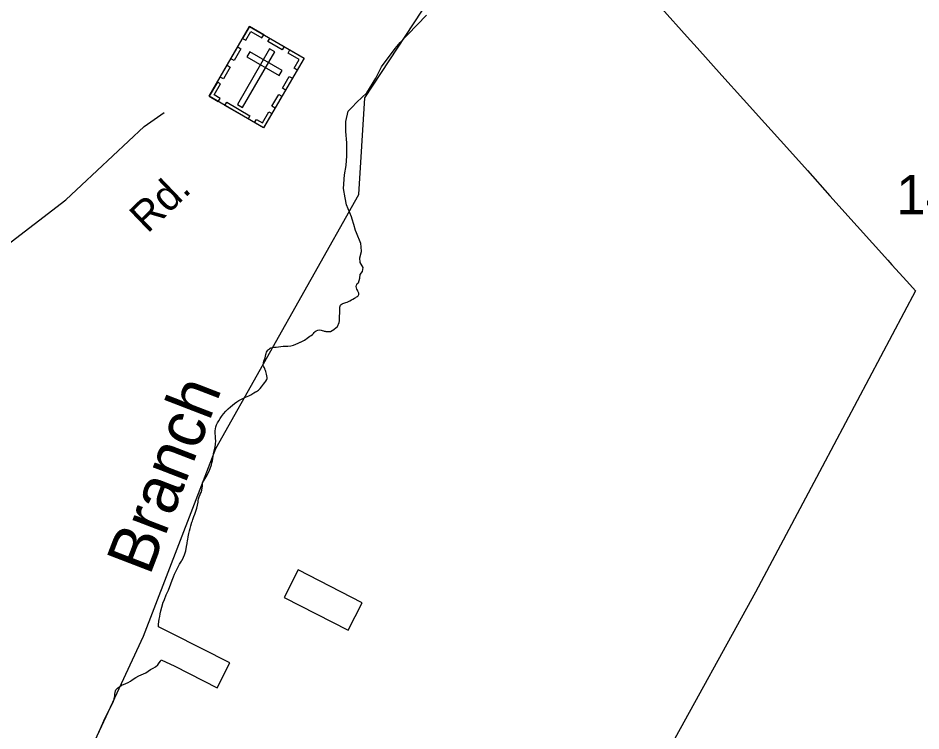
# Model space of a CAD drawing. Extents: x 2532689 to 2764727, y 536648 to 732970.
# Drawn here: x 2569863 to 2572716, y 677559 to 679813 of the extents above; entities that cross this region are included whole.
import ezdxf

# ---------------------------------------------------------------- set-up
doc = ezdxf.new("R2010")
doc.units = 0
for name, color, linetype in [('Exist Boundary Political City Limit New', 7, 'Continuous'), ('Exist Boundary Political City Limit New Hole', 7, 'Continuous'), ('Exist Cultural Cemetery CELL', 7, 'Continuous'), ('Exist Hydrographic Creek Single Shore', 7, 'Continuous'), ('Exist Hydrographic Creek Single Shore Label', 7, 'Continuous'), ('Exist Road Secondary Type 10 Attributed', 7, 'Continuous'), ('Exist Road Secondary Type 51 Label', 7, 'Continuous'), ('Exist Road Secondary Type 51 Number Label', 7, 'Continuous'), ('Map Preparation Boundary City Limit Buffer Line', 7, 'Continuous')]:
    doc.layers.add(name, color=color, linetype=linetype)

msp = doc.modelspace()

# ---------------------------------------------------------------- linework, layer by layer
at = {"layer": 'Exist Boundary Political City Limit New'}
for points in [[(2571895.8, 679844.9), (2571977.2, 679753.9)], [(2570860.8, 678828.7), (2570861.8, 678829.3), (2570872, 678838.1), (2570877.5, 678850), (2570878, 678855.6), (2570878, 678861), (2570878, 678864.5), (2570878, 678867.2), (2570878.5, 678872.9), (2570879, 678877.8), (2570879.5, 678882.4), (2570879.8, 678887.6), (2570879.8, 678893.1), (2570880, 678898.8), (2570880.2, 678902.1), (2570881.2, 678905.1), (2570883.5, 678907.6), (2570886.5, 678909.4), (2570889.2, 678910.4), (2570892, 678911.2), (2570898.5, 678913.4), (2570902.5, 678915.1), (2570905, 678916.2), (2570911.2, 678919.2), (2570916, 678921.7), (2570920.8, 678924.4), (2570926.2, 678927.6), (2570929.8, 678929.6), (2570932.5, 678931.2), (2570935.2, 678933.2), (2570937, 678935.1), (2570938.5, 678937.1), (2570939.5, 678939.2), (2570939.8, 678941), (2570939.5, 678942.9), (2570938.8, 678945.2), (2570936.8, 678949.8), (2570935, 678953.2), (2570933.5, 678956.4), (2570932.2, 678960.2), (2570931.5, 678964.3), (2570932, 678968.4), (2570933, 678971.1), (2570934.8, 678973.4), (2570937.5, 678975.6), (2570938.5, 678976.2), (2570943, 678991.2), (2570944.2, 679001.9), (2570950.8, 679011.8), (2570953.5, 679024.9), (2570944.2, 679040.6), (2570942.8, 679054.8), (2570947.5, 679075.3), (2570946.8, 679089.6), (2570946.2, 679100.6), (2570932.2, 679134.4), (2570929.5, 679141.2), (2570924, 679160.1), (2570919, 679177.2), (2570916, 679184.8), (2570901, 679222.8), (2570896.8, 679244.4), (2570890.8, 679274.4), (2570894, 679317.2), (2570899, 679347.2), (2570902, 679378), (2570902, 679418.4), (2570898.2, 679454.4), (2570898.2, 679485.6), (2570906.2, 679518.8), (2570917.2, 679530.4), (2570933, 679547.2), (2570965, 679576.4), (2570992.8, 679622.8), (2571006.8, 679650.2), (2571011.5, 679659.2), (2571054, 679717.2), (2571070.5, 679735.4), (2571094.2, 679761.2), (2571153.5, 679822.8)], [(2571977.2, 679753.9), (2572008.8, 679718.9), (2572087, 679631.7), (2572155, 679556), (2572222, 679481.3), (2572291.8, 679403.5), (2572356.8, 679331.1), (2572428.2, 679251.3), (2572514.2, 679155.6), (2572611.2, 679047.3), (2572624.2, 679033), (2572670.8, 678981.1), (2572698.2, 678950.5), (2572403.2, 678393.7), (2572193.2, 677997.9), (2571626.5, 676969)], [(2570511.5, 678561.6), (2570519.8, 678570.5), (2570527, 678577.4), (2570534, 678583.6), (2570540.2, 678588.8), (2570547, 678594.1), (2570554, 678599.2), (2570560.2, 678603.4), (2570566.8, 678607.2), (2570574.8, 678611.2), (2570581.2, 678614.1), (2570587, 678616.4), (2570592.2, 678618.8), (2570598.5, 678622.2), (2570604.8, 678626), (2570607.8, 678627.7), (2570613, 678630.8), (2570616.5, 678632.8), (2570622.2, 678636.5), (2570624.5, 678638.7), (2570628, 678642), (2570632.2, 678647.1), (2570635.2, 678651.7), (2570638.2, 678656), (2570642, 678660.6), (2570645.8, 678665.4), (2570648.8, 678670.4), (2570649.8, 678673.6), (2570649.8, 678677.1), (2570649.2, 678681.6), (2570648, 678687.1), (2570646.8, 678691.3), (2570645.5, 678695.2), (2570644.2, 678699), (2570643, 678703.1), (2570642.5, 678704.3), (2570641.2, 678707.2), (2570639.5, 678710.1), (2570638, 678712.9), (2570637.2, 678716.4), (2570637.8, 678723.2), (2570639.5, 678728.8), (2570641.5, 678734), (2570643.2, 678738.7), (2570644.8, 678743.7), (2570646.2, 678749.2), (2570647.2, 678753), (2570648, 678756.5), (2570650, 678760), (2570652.2, 678762.9), (2570654.5, 678765.2), (2570656.8, 678767.2), (2570658.2, 678768.4), (2570659.8, 678769.4), (2570660.5, 678769.7), (2570662, 678770.4), (2570667.8, 678772), (2570672.5, 678772.6), (2570675.8, 678772.7), (2570678, 678772.8), (2570686, 678773.6), (2570693.2, 678774.6), (2570700, 678775.2), (2570707.2, 678775.2), (2570715.2, 678775.4), (2570724.2, 678776.8), (2570732.8, 678779.2), (2570740, 678781.8), (2570747.5, 678785.2), (2570753.8, 678788), (2570755, 678788.5), (2570761.8, 678791.6), (2570768, 678794.8), (2570771.8, 678797.3), (2570776, 678800.3), (2570776.5, 678800.7), (2570780.8, 678804), (2570785.2, 678807.2), (2570789, 678809.8), (2570792.8, 678812.8), (2570795.8, 678815.8), (2570798.8, 678818.8), (2570801.5, 678821.6), (2570805.2, 678824.7), (2570809.8, 678826.8), (2570815.5, 678827.2), (2570820.2, 678826.5), (2570824, 678825.3), (2570828, 678824), (2570830.5, 678823.3), (2570833, 678822.8), (2570835.2, 678822.4), (2570837.2, 678822.2), (2570839.5, 678822.1), (2570842, 678822), (2570843.2, 678822), (2570845, 678822), (2570847.2, 678822), (2570849.5, 678822), (2570860.8, 678828.7)], [(2570309, 677912.3), (2570310.5, 677920.8), (2570312.2, 677929.7), (2570314.2, 677939.1), (2570317.2, 677950.9), (2570320.2, 677961.9), (2570320.5, 677962.9), (2570325, 677974.8), (2570331.2, 677989.4), (2570338.2, 678004.6), (2570345.8, 678024), (2570349.5, 678035.5), (2570353.5, 678046.8), (2570357, 678055.2), (2570361, 678063.6), (2570366.2, 678073.6), (2570373.2, 678085.9), (2570379.2, 678095.8), (2570380.2, 678097.6), (2570384.2, 678105.1), (2570385.8, 678108.6), (2570388.8, 678116.1), (2570392.5, 678128.3), (2570395.5, 678141.9), (2570397, 678152.2), (2570398.2, 678161.8), (2570398.8, 678164.7), (2570400.2, 678172.8), (2570402.5, 678182.9), (2570404.8, 678191.6), (2570406.8, 678199.6), (2570409, 678208), (2570412, 678219), (2570413.5, 678223.7), (2570414.8, 678227.6), (2570418, 678236.9), (2570420.8, 678244.1), (2570421, 678244.8), (2570424, 678253.6), (2570427.2, 678263.8), (2570429.8, 678273.2), (2570431.5, 678282), (2570431.8, 678284), (2570432.2, 678287.1), (2570433, 678292.6), (2570434.8, 678299.2), (2570438, 678307.1), (2570438.5, 678308.1), (2570441, 678313.4), (2570443.5, 678320), (2570445, 678327.8), (2570445.2, 678332.9), (2570445.5, 678335.7), (2570445.5, 678343.6), (2570450.5, 678351.9), (2570456.8, 678362.1), (2570466.8, 678380.9), (2570474, 678400.4), (2570475.5, 678406.4), (2570476.8, 678412.6), (2570478, 678420.4), (2570479.2, 678428.4), (2570480.5, 678434.8), (2570481.5, 678440.8), (2570484, 678451.9), (2570486.2, 678463.9), (2570486.5, 678466.2), (2570487.2, 678476), (2570487, 678483.3), (2570486.8, 678485.4), (2570486.2, 678490.6), (2570486, 678499.6), (2570486, 678507.8), (2570486.2, 678514.6), (2570487.5, 678520.8), (2570489.8, 678526.8), (2570493, 678533), (2570496.8, 678539.2), (2570501, 678546.6), (2570505.2, 678553.8), (2570511.5, 678561.6)], [(2570118, 677555.1), (2570123, 677566.7), (2570126.2, 677574.4), (2570133.5, 677591), (2570141, 677606.7), (2570143.2, 677611.1), (2570145.2, 677615.3), (2570149.8, 677624.2), (2570154.8, 677633.5), (2570158.2, 677639.8), (2570161.5, 677646), (2570164.2, 677653.5), (2570166, 677659.8), (2570166.8, 677663), (2570167.5, 677665.3), (2570168.2, 677670.7), (2570168.5, 677673.3), (2570168.8, 677675.7), (2570169.2, 677680.9), (2570170.8, 677685.9), (2570172, 677688.9), (2570173.8, 677691.6), (2570176.8, 677694.3), (2570177.2, 677694.7), (2570184, 677699.7), (2570190.2, 677703.4), (2570192.2, 677704.4), (2570196.2, 677706.3), (2570203.2, 677709.1), (2570210.8, 677712.2), (2570218.2, 677716.3), (2570223.5, 677720.2), (2570228.5, 677724.1), (2570230, 677725.2), (2570234.8, 677728.3), (2570244, 677732.9), (2570252, 677736.1), (2570259.5, 677739.1), (2570266.5, 677742.9), (2570273.8, 677747.6), (2570281.5, 677752.8), (2570289.5, 677757.4), (2570297, 677761.8), (2570304, 677768.3), (2570309, 677774), (2570312.8, 677779.3), (2570314.8, 677783.9), (2570357.8, 677763.4), (2570492.2, 677695.3), (2570532, 677774.2), (2570350.8, 677865.9), (2570306.2, 677888.6), (2570306.8, 677896), (2570307.8, 677904.8), (2570309, 677912.3)]]:
    msp.add_lwpolyline(points, dxfattribs=at)
at = {"layer": 'Exist Boundary Political City Limit New Hole'}
msp.add_lwpolyline([(2570703.5, 677981.3), (2570906.2, 677877.3), (2570950.2, 677964.2), (2570747.5, 678068.6), (2570703.5, 677981.3)], dxfattribs=at)
at = {"layer": 'Exist Cultural Cemetery CELL'}
for points in [[(2570594.2, 679786.1), (2570766.4, 679686.3), (2570638.8, 679466), (2570466.5, 679565.8)], [(2570572.4, 679748.7), (2570582.3, 679743), (2570598.4, 679770.8), (2570633.5, 679750.5), (2570639.1, 679760.1), (2570594.2, 679786.1)], [(2570658.2, 679749), (2570703.1, 679723), (2570697.4, 679713.1), (2570652.5, 679739.1)], [(2570535.2, 679684.5), (2570557, 679722), (2570566.8, 679716.3), (2570545.1, 679678.8)], [(2570673.8, 679706.1), (2570657.6, 679715.5), (2570556, 679540), (2570572.1, 679530.7)], [(2570595.3, 679706.8), (2570586, 679690.6), (2570687.9, 679631.6), (2570697.2, 679647.8)], [(2570744.7, 679648.8), (2570734.9, 679654.5), (2570751.1, 679682.3), (2570716, 679702.6), (2570721.5, 679712.3), (2570766.4, 679686.2)], [(2570501.5, 679626.3), (2570523.2, 679663.8), (2570533.1, 679658.1), (2570511.4, 679620.6)], [(2570698.2, 679591.3), (2570719.9, 679628.7), (2570729.8, 679623), (2570708.1, 679585.5)], [(2570495.1, 679549.3), (2570500.9, 679559.2), (2570481.9, 679570.2), (2570502.1, 679605.2), (2570492.5, 679610.8), (2570466.5, 679565.9)], [(2570665.1, 679534.2), (2570686.9, 679571.7), (2570696.7, 679566), (2570675, 679528.5)], [(2570522, 679546.9), (2570595.4, 679504.4), (2570589.7, 679494.5), (2570516.3, 679537.1)], [(2570610.1, 679482.6), (2570615.8, 679492.6), (2570634.9, 679481.5), (2570655.1, 679516.5), (2570664.8, 679510.9), (2570638.8, 679466)]]:
    msp.add_lwpolyline(points, close=True, dxfattribs=at)
at = {"layer": 'Exist Hydrographic Creek Single Shore'}
msp.add_lwpolyline([(2569856.8, 677104.4), (2570050.6, 677410.2), (2570258.8, 677858.6), (2570487.6, 678452.2), (2570939.7, 679255.2), (2570958.6, 679561.3), (2571241.8, 679993.1), (2571271.7, 680151.9), (2571468.8, 680297.7), (2571540.7, 680441.8), (2571618.7, 680717.5), (2571692.7, 680802.5), (2571973.6, 680925.5), (2572037.6, 681026.6), (2572130.7, 681417.8), (2572115.7, 681719.2), (2572080.6, 681842.6), (2572061.6, 682360.5), (2571991.7, 682557.9), (2571751.7, 682869.9)], dxfattribs=at)
at = {"layer": 'Exist Road Secondary Type 10 Attributed'}
msp.add_lwpolyline([(2569071.9, 678518.3), (2569725.7, 679018.3), (2570013.9, 679238.7), (2570261.6, 679469.9), (2570324.1, 679514.6)], dxfattribs=at)
at = {"layer": 'Map Preparation Boundary City Limit Buffer Line'}
for points in [[(2571895.8, 679844.9), (2571977.2, 679753.9)], [(2570860.8, 678828.7), (2570861.8, 678829.3), (2570872, 678838.1), (2570877.5, 678850), (2570878, 678855.6), (2570878, 678861), (2570878, 678864.5), (2570878, 678867.2), (2570878.5, 678872.9), (2570879, 678877.8), (2570879.5, 678882.4), (2570879.8, 678887.6), (2570879.8, 678893.1), (2570880, 678898.8), (2570880.2, 678902.1), (2570881.2, 678905.1), (2570883.5, 678907.6), (2570886.5, 678909.4), (2570889.2, 678910.4), (2570892, 678911.2), (2570898.5, 678913.4), (2570902.5, 678915.1), (2570905, 678916.2), (2570911.2, 678919.2), (2570916, 678921.7), (2570920.8, 678924.4), (2570926.2, 678927.6), (2570929.8, 678929.6), (2570932.5, 678931.2), (2570935.2, 678933.2), (2570937, 678935.1), (2570938.5, 678937.1), (2570939.5, 678939.2), (2570939.8, 678941), (2570939.5, 678942.9), (2570938.8, 678945.2), (2570936.8, 678949.8), (2570935, 678953.2), (2570933.5, 678956.4), (2570932.2, 678960.2), (2570931.5, 678964.3), (2570932, 678968.4), (2570933, 678971.1), (2570934.8, 678973.4), (2570937.5, 678975.6), (2570938.5, 678976.2), (2570943, 678991.2), (2570944.2, 679001.9), (2570950.8, 679011.8), (2570953.5, 679024.9), (2570944.2, 679040.6), (2570942.8, 679054.8), (2570947.5, 679075.3), (2570946.8, 679089.6), (2570946.2, 679100.6), (2570932.2, 679134.4), (2570929.5, 679141.2), (2570924, 679160.1), (2570919, 679177.2), (2570916, 679184.8), (2570901, 679222.8), (2570896.8, 679244.4), (2570890.8, 679274.4), (2570894, 679317.2), (2570899, 679347.2), (2570902, 679378), (2570902, 679418.4), (2570898.2, 679454.4), (2570898.2, 679485.6), (2570906.2, 679518.8), (2570917.2, 679530.4), (2570933, 679547.2), (2570965, 679576.4), (2570992.8, 679622.8), (2571006.8, 679650.2), (2571011.5, 679659.2), (2571054, 679717.2), (2571070.5, 679735.4), (2571094.2, 679761.2), (2571153.5, 679822.8)], [(2571977.2, 679753.9), (2572008.8, 679718.9), (2572087, 679631.7), (2572155, 679556), (2572222, 679481.3), (2572291.8, 679403.5), (2572356.8, 679331.1), (2572428.2, 679251.3), (2572514.2, 679155.6), (2572611.2, 679047.3), (2572624.2, 679033), (2572670.8, 678981.1), (2572698.2, 678950.5), (2572403.2, 678393.7), (2572193.2, 677997.9), (2571626.5, 676969)], [(2570511.5, 678561.6), (2570519.8, 678570.5), (2570527, 678577.4), (2570534, 678583.6), (2570540.2, 678588.8), (2570547, 678594.1), (2570554, 678599.2), (2570560.2, 678603.4), (2570566.8, 678607.2), (2570574.8, 678611.2), (2570581.2, 678614.1), (2570587, 678616.4), (2570592.2, 678618.8), (2570598.5, 678622.2), (2570604.8, 678626), (2570607.8, 678627.7), (2570613, 678630.8), (2570616.5, 678632.8), (2570622.2, 678636.5), (2570624.5, 678638.7), (2570628, 678642), (2570632.2, 678647.1), (2570635.2, 678651.7), (2570638.2, 678656), (2570642, 678660.6), (2570645.8, 678665.4), (2570648.8, 678670.4), (2570649.8, 678673.6), (2570649.8, 678677.1), (2570649.2, 678681.6), (2570648, 678687.1), (2570646.8, 678691.3), (2570645.5, 678695.2), (2570644.2, 678699), (2570643, 678703.1), (2570642.5, 678704.3), (2570641.2, 678707.2), (2570639.5, 678710.1), (2570638, 678712.9), (2570637.2, 678716.4), (2570637.8, 678723.2), (2570639.5, 678728.8), (2570641.5, 678734), (2570643.2, 678738.7), (2570644.8, 678743.7), (2570646.2, 678749.2), (2570647.2, 678753), (2570648, 678756.5), (2570650, 678760), (2570652.2, 678762.9), (2570654.5, 678765.2), (2570656.8, 678767.2), (2570658.2, 678768.4), (2570659.8, 678769.4), (2570660.5, 678769.7), (2570662, 678770.4), (2570667.8, 678772), (2570672.5, 678772.6), (2570675.8, 678772.7), (2570678, 678772.8), (2570686, 678773.6), (2570693.2, 678774.6), (2570700, 678775.2), (2570707.2, 678775.2), (2570715.2, 678775.4), (2570724.2, 678776.8), (2570732.8, 678779.2), (2570740, 678781.8), (2570747.5, 678785.2), (2570753.8, 678788), (2570755, 678788.5), (2570761.8, 678791.6), (2570768, 678794.8), (2570771.8, 678797.3), (2570776, 678800.3), (2570776.5, 678800.7), (2570780.8, 678804), (2570785.2, 678807.2), (2570789, 678809.8), (2570792.8, 678812.8), (2570795.8, 678815.8), (2570798.8, 678818.8), (2570801.5, 678821.6), (2570805.2, 678824.7), (2570809.8, 678826.8), (2570815.5, 678827.2), (2570820.2, 678826.5), (2570824, 678825.3), (2570828, 678824), (2570830.5, 678823.3), (2570833, 678822.8), (2570835.2, 678822.4), (2570837.2, 678822.2), (2570839.5, 678822.1), (2570842, 678822), (2570843.2, 678822), (2570845, 678822), (2570847.2, 678822), (2570849.5, 678822), (2570860.8, 678828.7)], [(2570309, 677912.3), (2570310.5, 677920.8), (2570312.2, 677929.7), (2570314.2, 677939.1), (2570317.2, 677950.9), (2570320.2, 677961.9), (2570320.5, 677962.9), (2570325, 677974.8), (2570331.2, 677989.4), (2570338.2, 678004.6), (2570345.8, 678024), (2570349.5, 678035.5), (2570353.5, 678046.8), (2570357, 678055.2), (2570361, 678063.6), (2570366.2, 678073.6), (2570373.2, 678085.9), (2570379.2, 678095.8), (2570380.2, 678097.6), (2570384.2, 678105.1), (2570385.8, 678108.6), (2570388.8, 678116.1), (2570392.5, 678128.3), (2570395.5, 678141.9), (2570397, 678152.2), (2570398.2, 678161.8), (2570398.8, 678164.7), (2570400.2, 678172.8), (2570402.5, 678182.9), (2570404.8, 678191.6), (2570406.8, 678199.6), (2570409, 678208), (2570412, 678219), (2570413.5, 678223.7), (2570414.8, 678227.6), (2570418, 678236.9), (2570420.8, 678244.1), (2570421, 678244.8), (2570424, 678253.6), (2570427.2, 678263.8), (2570429.8, 678273.2), (2570431.5, 678282), (2570431.8, 678284), (2570432.2, 678287.1), (2570433, 678292.6), (2570434.8, 678299.2), (2570438, 678307.1), (2570438.5, 678308.1), (2570441, 678313.4), (2570443.5, 678320), (2570445, 678327.8), (2570445.2, 678332.9), (2570445.5, 678335.7), (2570445.5, 678343.6), (2570450.5, 678351.9), (2570456.8, 678362.1), (2570466.8, 678380.9), (2570474, 678400.4), (2570475.5, 678406.4), (2570476.8, 678412.6), (2570478, 678420.4), (2570479.2, 678428.4), (2570480.5, 678434.8), (2570481.5, 678440.8), (2570484, 678451.9), (2570486.2, 678463.9), (2570486.5, 678466.2), (2570487.2, 678476), (2570487, 678483.3), (2570486.8, 678485.4), (2570486.2, 678490.6), (2570486, 678499.6), (2570486, 678507.8), (2570486.2, 678514.6), (2570487.5, 678520.8), (2570489.8, 678526.8), (2570493, 678533), (2570496.8, 678539.2), (2570501, 678546.6), (2570505.2, 678553.8), (2570511.5, 678561.6)], [(2570703.5, 677981.3), (2570906.2, 677877.3), (2570950.2, 677964.2), (2570747.5, 678068.6), (2570703.5, 677981.3)], [(2570118, 677555.1), (2570123, 677566.7), (2570126.2, 677574.4), (2570133.5, 677591), (2570141, 677606.7), (2570143.2, 677611.1), (2570145.2, 677615.3), (2570149.8, 677624.2), (2570154.8, 677633.5), (2570158.2, 677639.8), (2570161.5, 677646), (2570164.2, 677653.5), (2570166, 677659.8), (2570166.8, 677663), (2570167.5, 677665.3), (2570168.2, 677670.7), (2570168.5, 677673.3), (2570168.8, 677675.7), (2570169.2, 677680.9), (2570170.8, 677685.9), (2570172, 677688.9), (2570173.8, 677691.6), (2570176.8, 677694.3), (2570177.2, 677694.7), (2570184, 677699.7), (2570190.2, 677703.4), (2570192.2, 677704.4), (2570196.2, 677706.3), (2570203.2, 677709.1), (2570210.8, 677712.2), (2570218.2, 677716.3), (2570223.5, 677720.2), (2570228.5, 677724.1), (2570230, 677725.2), (2570234.8, 677728.3), (2570244, 677732.9), (2570252, 677736.1), (2570259.5, 677739.1), (2570266.5, 677742.9), (2570273.8, 677747.6), (2570281.5, 677752.8), (2570289.5, 677757.4), (2570297, 677761.8), (2570304, 677768.3), (2570309, 677774), (2570312.8, 677779.3), (2570314.8, 677783.9), (2570357.8, 677763.4), (2570492.2, 677695.3), (2570532, 677774.2), (2570350.8, 677865.9), (2570306.2, 677888.6), (2570306.8, 677896), (2570307.8, 677904.8), (2570309, 677912.3)]]:
    msp.add_lwpolyline(points, dxfattribs=at)

# ---------------------------------------------------------------- texts
at = {"layer": 'Exist Hydrographic Creek Single Shore Label'}
msp.add_text('Branch', height=150, rotation=68.9204, dxfattribs=at).set_placement((2570278.7, 678047.1))
at = {"layer": 'Exist Road Secondary Type 51 Label'}
msp.add_text('Rd.', height=95, rotation=43.7933, dxfattribs=at).set_placement((2570271.8, 679129.8))
at = {"layer": 'Exist Road Secondary Type 51 Number Label'}
msp.add_text('1439', height=125, rotation=359.94, dxfattribs=at).set_placement((2572637.8, 679192.4))

doc.saveas('drawing.dxf')
